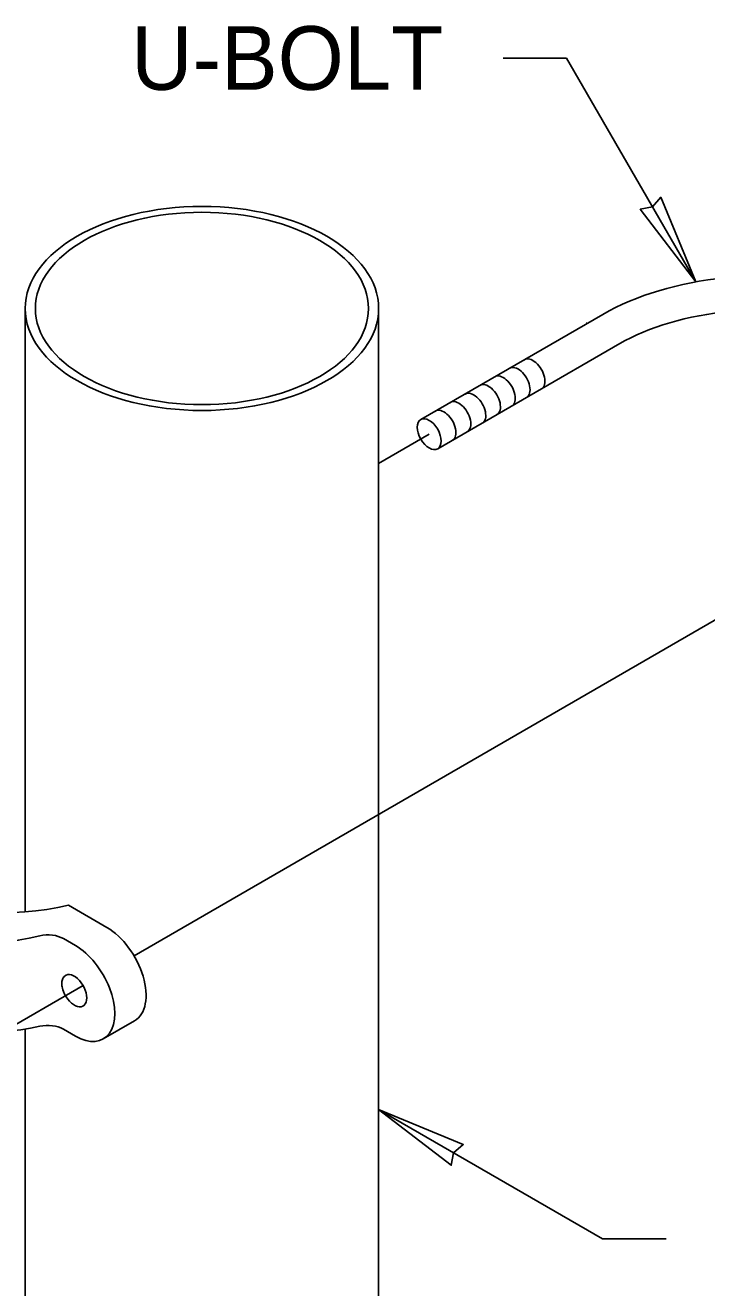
# Model space of a CAD drawing. Extents: x 99862 to 103151, y 100000 to 105076.
# Drawn here: x 101226.9 to 101398.3, y 100218.1 to 100535.6 of the extents above; entities that cross this region are included whole.
import ezdxf

# ---------------------------------------------------------------- set-up
doc = ezdxf.new("R2010")
doc.units = 0
for name, color, linetype in [('Level 12', 7, 'Continuous'), ('Level 15', 7, 'Continuous'), ('Level 16', 7, 'Continuous'), ('Level 20', 7, 'Continuous'), ('Level 5', 7, 'Continuous'), ('Level 8', 7, 'Continuous')]:
    doc.layers.add(name, color=color, linetype=linetype)

msp = doc.modelspace()

# ---------------------------------------------------------------- linework, layer by layer
at = {"layer": 'Level 12'}
for p, q in [((101372.14, 100462.86), (101326.38, 100436.43)), ((101330.63, 100429.07), (101376.39, 100455.5))]:
    msp.add_line(p, q, dxfattribs=at)
for centre, major_axis, ratio, start_param, end_param in [((101370.23, 100457.04), (2.15, -3.67), 0.581626, 3.13818, 3.141605), ((101365.66, 100454.36), (2.13, -3.68), 0.57735, 3.133556, 3.157063), ((101354.57, 100447.8), (2.13, -3.68), 0.57735, 0.003717, 3.155143), ((101347.12, 100443.5), (2.13, -3.68), 0.57735, 0.003717, 3.15362), ((101350.83, 100445.65), (2.13, -3.68), 0.57735, 0.003717, 3.154413), ((101343.39, 100441.35), (2.13, -3.68), 0.57735, 0.003717, 3.152743), ((101335.95, 100437.05), (2.13, -3.68), 0.57735, 0.003717, 3.150566), ((101339.7, 100439.15), (2.13, -3.68), 0.57735, 0.003717, 3.151747), ((101332.19, 100434.88), (2.13, -3.68), 0.57735, 0.003717, 3.149026)]:
    msp.add_ellipse(centre, major_axis=major_axis, ratio=ratio, start_param=start_param, end_param=end_param, dxfattribs=at)
msp.add_ellipse((101328.49, 100432.74), major_axis=(2.13, -3.68), ratio=0.57735, dxfattribs=at)
for points in [[(101452.77, 100411.76), (101460.2, 100416.12), (101470.27, 100426.38), (101471.04, 100443.15), (101461.3, 100458.77), (101438.63, 100471.21), (101402.15, 100474.14), (101380.45, 100467.66), (101372.14, 100462.86)], [(101376.39, 100455.5), (101383.61, 100459.67), (101403.53, 100465.61), (101437.16, 100462.63), (101454.85, 100452.2), (101461.58, 100442.22), (101462.65, 100434.97), (101458.24, 100426.24), (101452.08, 100421.19), (101448.47, 100419.09)]]:
    msp.add_open_spline(points, degree=3, dxfattribs=at)
at = {"layer": 'Level 15'}
for p, q in [((101347.05, 100527.33), (101363.05, 100527.33)), ((101395.55, 100471.04), (101363.05, 100527.33)), ((101315.77, 100262.91), (101372.06, 100230.41)), ((101388.06, 100230.41), (101372.06, 100230.41))]:
    msp.add_line(p, q, dxfattribs=at)
for points in [[(101395.55, 100471.04), (101381.55, 100489.32), (101384.66, 100489.89), (101386.72, 100492.3)], [(101315.77, 100262.91), (101334.04, 100248.91), (101334.62, 100252.02), (101337.03, 100254.08)]]:
    msp.add_lwpolyline(points, close=True, dxfattribs=at)
at = {"layer": 'Level 16'}
for p, q in [((101328.49, 100432.74), (101315.77, 100425.4)), ((101408.97, 100391.02), (101254.27, 100301.55)), ((101241.43, 100294.12), (101208.05, 100274.82))]:
    msp.add_line(p, q, dxfattribs=at)
at = {"layer": 'Level 5'}
for p, q in [((101226.89, 100464.35), (101226.89, 100312.59)), ((101315.77, 100162.9), (101315.77, 100464.35)), ((101226.89, 100283.15), (101226.89, 100162.9))]:
    msp.add_line(p, q, dxfattribs=at)
for major_axis in [(-44.44, 0), (41.89, 0)]:
    msp.add_ellipse((101271.33, 100464.35), major_axis=major_axis, ratio=0.57735, dxfattribs=at)
at = {"layer": 'Level 8'}
for p, q in [((101237.75, 100314.27), (101247.42, 100308.69)), ((101239.53, 100304.14), (101236.49, 100305.89)), ((101239.53, 100281.37), (101236.49, 100283.12)), ((101246.51, 100280.68), (101254.39, 100285.23))]:
    msp.add_line(p, q, dxfattribs=at)
for centre, major_axis, start_param, end_param in [((101220.91, 100338.02), (44.44, 0), 4.086377, 5.101018), ((101215.47, 100327.93), (-40.3, -1.11), 0.824653, 1.938346), ((101247.42, 100297.31), (6.97, -12.07), 6.283185, 8.63938), ((101232.55, 100303.62), (5.58, 0), 0.785398, 1.938346), ((101239.53, 100292.75), (-6.97, 12.07), 2.356194, 5.497787), ((101239.23, 100292.79), (-2.22, 3.85), 1.299813, 6.554168), ((101216.06, 100305.57), (-40.31, 0), 0.956936, 1.938346), ((101232.55, 100280.85), (5.58, 0), 0.785398, 1.938346)]:
    msp.add_ellipse(centre, major_axis=major_axis, ratio=0.57735, start_param=start_param, end_param=end_param, dxfattribs=at)
msp.add_open_spline([(101236.49, 100296.16), (101236.23, 100295.77), (101236.07, 100295.22), (101236.07, 100293.98), (101236.23, 100293.29), (101236.49, 100292.59)], degree=3, dxfattribs=at)

# ---------------------------------------------------------------- texts
at = {"layer": 'Level 20'}
msp.add_text('U-BOLT', height=16, dxfattribs=at).set_placement((101253.53, 100519.33))

doc.saveas('drawing.dxf')
